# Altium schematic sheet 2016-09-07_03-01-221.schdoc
size 361 x 125 mm; SheetNumber: 1; SheetTotal: 1
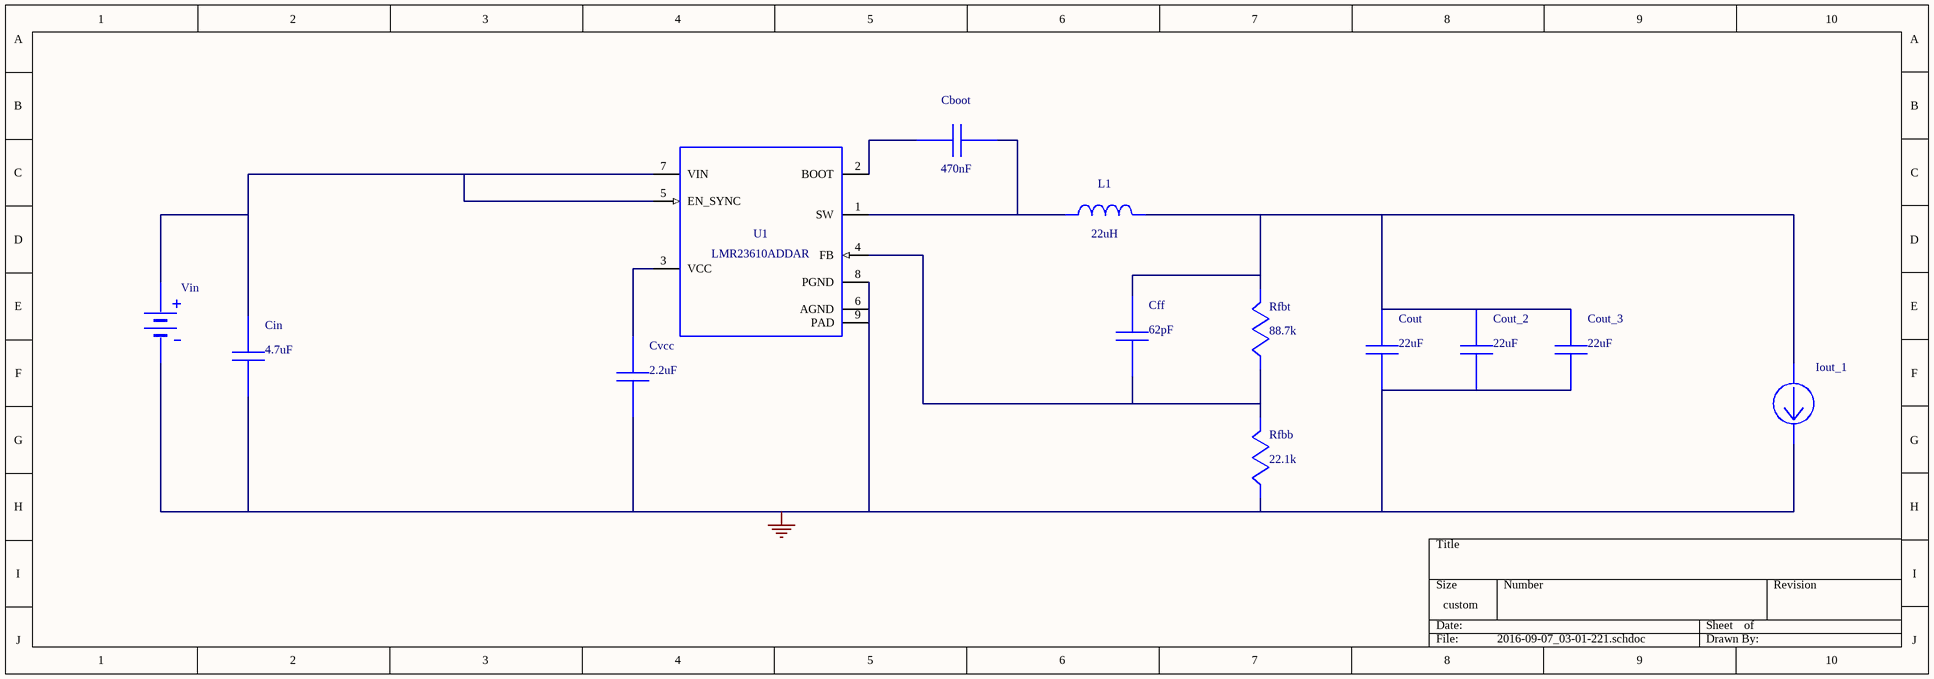
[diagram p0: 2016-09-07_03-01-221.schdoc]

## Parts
Cboot  value 470nF  (hidden comment: GRM21BR72A474KA73L)
Cff  value 62pF  (hidden comment: CL21C620JBANNNC)
Cin  value 4.7uF  (hidden comment: GRM32ER71H475KA88L)
Cout  value 22uF  (hidden comment: GRM31CR61A226KE19L)
Cout_2  value 22uF  (hidden comment: GRM31CR61A226KE19L)
Cout_3  value 22uF  (hidden comment: GRM31CR61A226KE19L)
Cvcc  value 2.2uF  (hidden comment: GRM188R60J225KE19D)
Iout_1  WB_CURRENT_LOAD  (value not drawn)
L1  value 22uH  (hidden comment: SRN6045-220M)
Rfbb  value 22.1k  (hidden comment: ERJ-6ENF2212V)
Rfbt  value 88.7k  (hidden comment: ERJ-6ENF8872V)
U1  LMR23610ADDAR
Vin  WB_BATTERY  (value not drawn)

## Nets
0: Cin.2 Cout.2 Cout_2.2 Cout_3.2 Cvcc.2 Iout_1.2(-) Rfbb.2 U1.6(AGND) U1.8(PGND) U1.9(PAD) Vin.2(-)
NetCboot_1: Cboot.1 U1.2(BOOT)
NetCboot_2: Cboot.2 L1.1 U1.1(SW)
NetCff_1: Cff.1 Cout.1 Cout_2.1 Cout_3.1 Iout_1.1(+) L1.2 Rfbt.1
NetCff_2: Cff.2 Rfbb.1 Rfbt.2 U1.4(FB)
NetCin_1: Cin.1 U1.5(EN_SYNC) U1.7(VIN) Vin.1(+)
NetCvcc_1: Cvcc.1 U1.3(VCC)

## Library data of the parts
Cboot = GRM21BR72A474KA73L: GRM21BR72A474KA7; Manufacturer Name: MuRata
Cff = CL21C620JBANNNC: Manufacturer Name: Samsung Electro-Mechanics
Cin = GRM32ER71H475KA88L: GRM32ER71H475KA8; Manufacturer Name: MuRata
Cout Cout_2 Cout_3 = GRM31CR61A226KE19L: GRM31CR61A226KE1; Manufacturer Name: MuRata
Cvcc = GRM188R60J225KE19D: GRM188R60J225KE1; Manufacturer Name: MuRata
L1 = SRN6045-220M: Manufacturer Name: Bourns
Rfbb = ERJ-6ENF2212V: Manufacturer Name: Panasonic
Rfbt = ERJ-6ENF8872V: Manufacturer Name: Panasonic
U1 = LMR23610ADDAR: Manufacturer Name: Texas Instruments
